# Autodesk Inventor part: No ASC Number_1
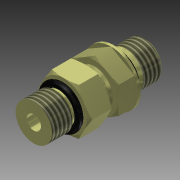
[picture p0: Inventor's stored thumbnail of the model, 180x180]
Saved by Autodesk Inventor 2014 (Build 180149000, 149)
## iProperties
Shininess: 20.0
Length Units: 11272
Angle Units: 11279
Time Units: 11290
Mass Units: 11286
Length Display Precision: 3
Angle Display Precision: 2
Company: Autodesk, Inc.
Created: 2001-10
Part Number: No ASC Number_1
Material: Steel, Mild
Description: FITTING; ST-GG4-S
Vendor: 0503-4-4
Document SubType Name: Modeling
Designer: Autodesk, Inc.
Density: 7.86 g/cm^3
Appearance: Yellow Zinc
Density: 7.86
Volumn: 2.786291585014959
Area: 20.936420168139023
PropertySet Name: Model Information
Control State: 0
Master: False
Checked Out: False
Last Check In By: JT
Last Check In Date: 2003-06-20
MODEL - 1: ---
MODEL - 2: ---
RAW MATERIAL: --------
SCALE:: 1=??
SIZE: 00 x 00 x 00
SUB-ASSY - 1: ------
SUB-ASSY - 1 - QUA: 1
SUB-ASSY - 2: ------
SUB-ASSY - 2 - QUA: 1
SYM. TO:: N/A
TEMPLATE CREATION: -- / __-__-__
Title: FITTING; ST-GG4-S
Author: Autodesk, Inc.
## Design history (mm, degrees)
sketch "Sketch1"
  geometry: L1 (8.249, 0)-(4.124, -7.144); L2 (4.124, -7.144)-(-4.124, -7.144); L3 (-4.124, -7.144)-(-8.249, 0); L4 (-8.249, 0)-(-4.124, 7.144); L5 (-4.124, 7.144)-(4.124, 7.144); L6 (4.124, 7.144)-(8.249, 0); 2 further points
  constraints: 12 end point, 1 coincident, 11 other
  dimensions: "d3" = 14.2875 distance between parallel lines of L3 L6 (= Hex_Size)
extrude "Hex Head" new body sketch "Sketch1" distance "d4" = 6.858 (= Hex_Thk); taper "d5" = 0 deg
sketch "Sketch2"
  geometry: L1 (-4.124, 6.858)-(-8.249, 6.858) reference; L2 (-4.124, 0)-(-8.249, 0) reference; L3 (-7.144, 0)-(-8.249, 0.515); L4 (-7.144, 6.858)-(-8.249, 6.343); L5 (-8.249, 6.858)-(-8.249, 6.343); L6 (-8.249, 0.515)-(-8.249, 0); L7 (-7.144, 6.858)-(-7.144, 0); L8 (0, 0)-(0, -4.932)
  constraints: 12 end point, 2 parallel, 2 perpendicular, 2 point on line
  dimensions: "d6" = 25 deg angle of L3 L2; "d7" = 25 deg angle of L1 L4; "d8" = 14.2875 diameter of L7 L8 (= Hex_Size)
revolve "Hex Head Material Removal" sketch "Sketch2" stored, may be unused: angle "d9" = 90 deg
sketch "Sketch8"
  geometry: L1 (0, 0)-(0, 19.901); L2 (4.623, 6.858)-(4.623, 8.839); L3 (4.623, 8.839)-(5.556, 9.773); L4 (5.556, 9.773)-(5.556, 16.002); L5 (5.556, 16.002)-(0, 16.002); L6 (4.124, 6.858)-(8.249, 6.858) reference; L7 (-4.124, 6.858)-(4.124, 6.858) reference; L8 (4.623, 6.858)-(0, 6.858); L9 (0, 6.858)-(0, 16.002)
  constraints: 14 end point, 1 collinear, 1 midpoint, 1 parallel, 1 perpendicular, 1 point on line, 1 vertical
  dimensions: "d31" = 11.1125 diameter of L4 L1 (= Oring_Thread_OD); "d32" = 9.2456 diameter of L2 L1 (= Oring_OD); "d33" = 7.1628 distance from line of L5 L2.end (= Oring_ThreadLength); "d35" = 45 deg angle of L2 L3; "d46" = 9.144 distance between parallel lines of L5 L6 (= Oring_Length)
revolve "Oring" sketch "Sketch8" stored, may be unused: angle "d36" = 90 deg
sketch "Sketch9"
  geometry: C1 r 5.556 at (0, 0) reference; C2 r 2.184 at (0, 0)
  constraints: 1 centre point, 1 coincident
  dimensions: "d37" = 4.3688 diameter of C2 (= Oring_ID)
extrude "Oring Hole" cut sketch "Sketch9" distance "d38" = 9.144 (= Oring_Length); taper "d39" = 0 deg
thread "Thread3" dims "d40" = 25.4, "d41" = 0
sketch "Sketch10"
  geometry: L1 (0, 0)-(0, 22.019); C1 r 0.953 at (5.575, 7.811)
  constraints: 2 end point, 1 centre point, 1 vertical
  dimensions: "d42" = 1.905 diameter of C1 (= Seal_Dia_W); "d43" = 7.8105 vertical distance of C1.centre L1.start (= Seal_Loc_A); "d44" = 5.5753 horizontal distance of C1.centre L1.start (= Seal_Loc_B)
revolve "Revolution4" sketch "Sketch10" stored, may be unused: angle "d45" = 90 deg
sketch "Sketch11"
  geometry: L1 (0, 0)-(0, -35.917); L2 (1.975, 0)-(1.975, 0); L3 (5.556, -2.81)-(5.556, -6.689); L4 (5.556, -6.689)-(4.648, -7.214); L5 (4.648, -7.214)-(4.648, -11.024); L6 (4.648, -11.024)-(5.556, -11.932); L7 (5.556, -11.932)-(5.556, -17.431); L8 (5.556, -17.431)-(4.699, -18.288); L9 (4.699, -18.288)-(0, -18.288); L10 (4.648, 0)-(4.648, -2.286); L11 (4.648, -2.286)-(5.556, -2.81); L12 (0, -18.288)-(0, 0); L13 (0, 0)-(4.648, 0); L14 (-5.556, 16.002)-(5.556, 16.002) reference
  constraints: 26 end point, 4 vertical, 3 perpendicular, 2 collinear, 1 point on line
  dimensions: "d52" = 60 deg angle of L5 L4; "d53" = 45 deg angle of L6 L5; "d54" = 60 deg angle of L3 L11; "d56" = 2.286 distance of L10.start L10.end (= Oring_Undercut_H_2); "d57" = 3.81 distance of L4.end L5.end (= Oring_Undercut_H1_2); "d58" = 9.2964 diameter of L10 L1 (= Oring_Undercut_G_2); "d59" = 9.2964 diameter of L5 L1 (= Oring_Undercut_G1_2); "d60" = 11.1125 diameter of L7 L1 (= Oring_Thread_OD_2); "d61" = 9.398 diameter of L8.end L1 (= Oring_Lip_V_2); "d63" = 7.2644 vertical distance of L8.end L5.end (= Oring_Threadlength_J3_2); "d64" = 18.288 distance from line of L9 L1.start (= I5_2)
revolve "Revolution5" sketch "Sketch11" stored, may be unused: angle "d62" = 90 deg
workplane "Work Plane1"
sketch "Sketch12"
  geometry: L1 (0, 8.249)-(7.144, 4.124); L2 (7.144, 4.124)-(7.144, -4.124); L3 (7.144, -4.124)-(0, -8.249); L4 (0, -8.249)-(-7.144, -4.124); L5 (-7.144, -4.124)-(-7.144, 4.124); L6 (-7.144, 4.124)-(0, 8.249); C1 r 5.556 at (0, 0); 2 further points
  constraints: 12 end point, 2 coincident, 1 centre point, 1 vertical alignment, 11 other
  dimensions: "d66" = 14.2875 distance between parallel lines of L6 L3 (derived); "d67" = 11.1125 diameter of C1 (derived)
extrude "Extrusion7" join sketch "Sketch12" distance "d68" = 5.842 (derived); taper "d69" = 0 deg
sketch "Sketch13"
  geometry: L1 (-4.699, -18.288)-(4.699, -18.288) reference; L2 (-13.494, -8.382)-(-7.144, -8.382); L3 (-7.144, -8.382)-(-13.494, -6.681); L4 (-13.494, -6.681)-(-13.494, -8.382); L5 (-7.144, -2.54)-(-13.494, -2.54); L6 (-13.494, -2.54)-(-13.494, -4.241); L7 (-13.494, -4.241)-(-7.144, -2.54); L8 (-7.144, -8.382)-(-7.144, -2.54); L9 (0, 0)-(0, -30.431)
  constraints: 16 end point, 3 parallel, 3 perpendicular, 1 collinear
  dimensions: "d70" = 15 deg angle of L3 L2; "d71" = 15 deg angle of L5 L7; "d72" = 14.2875 diameter of L8 L9 (derived); "d73" = 6.35 distance from line of L2.start L8; "d74" = 9.906 distance between parallel lines of L2 L1 (derived); "d75" = 5.842 distance between parallel lines of L5 L2 (derived)
revolve "Revolution6" sketch "Sketch13" stored, may be unused: angle "d76" = 90 deg
sketch "Sketch14"
  geometry: L1 (0, -8.249)-(3.572, -6.187) reference; L2 (3.572, -6.187)-(7.144, -4.124) reference; C1 r 5.556 at (0, 0); 2 further points
  constraints: 2 coincident, 1 centre point, 1 vertical alignment, 2 other
  dimensions: "d77" = 11.1125 diameter of C1 (derived)
extrude "Extrusion8" join sketch "Sketch14" distance "d79" = 0.79375; taper "d80" = 0 deg
thread "Thread4" dims "d81" = 25.4, "d82" = 0
sketch "Sketch15"
  geometry: L1 (-4.699, -18.288)-(4.699, -18.288) reference; L2 (0, 0)-(0, -23.609); C1 r 0.953 at (-5.601, -9.334)
  constraints: 2 end point, 1 centre point, 1 perpendicular
  dimensions: "d83" = 1.905 diameter of C1 (derived); "d84" = 8.9535 distance from line of C1.centre L1 (derived); "d85" = 11.2014 diameter of C1.centre L2 (derived)
revolve "Revolution7" sketch "Sketch15" stored, may be unused: angle "d86" = 90 deg
sketch "Sketch16"
  geometry: C1 r 2.184 at (0, 0); 1 further point
  constraints: 1 centre point, 1 coincident
  dimensions: "d87" = 4.3688 diameter of C1 (derived)
extrude "Extrusion9" cut sketch "Sketch16" distance "d88" = 25.146 (derived); taper "d89" = 0 deg
body "Solid1"
other parameters: "Hex_Size" = 14.2875 [user parameter; used in 2 equation terms], "Hex_Thk" = 6.858 [user parameter; used in 3 equation terms], "Jic_Length" = 15.24 (= Length_LL - Hex_Thk) [user parameter], "Jic_ThreadLength" = 7.1628 [user parameter], "Length_LL" = 22.098 [user parameter; used in 2 equation terms], "Jic_Thread_OD" = 11.1125 [user parameter], "JIC_OD" = 9.2456 [user parameter], "Jic_Lip_OD" = 4.9022 [user parameter], "Jic_ID" = 4.3688 [user parameter], "Oring_Length" = 9.144 (= OAL_L5 - Length_LL) [user parameter; used in 2 equation terms], "OAL_L5" = 31.242 [user parameter; used in 1 equation term], "Oring_Thread_OD" = 11.1125 [user parameter; used in 1 equation term], "Oring_ID" = 4.3688 [user parameter; used in 1 equation term], "Oring_OD" = 9.2456 [user parameter; used in 2 equation terms], "Oring_ThreadLength" = 7.1628 [user parameter; used in 1 equation term], "Seal_Dia_W" = 1.905 [user parameter; used in 3 equation terms], "Seal_Loc_A" = 7.8105 (= Hex_Thk + 0.5 x Seal_Dia_W) [user parameter; used in 1 equation term], "Seal_Loc_B" = 5.5753 (= 0.5 x Oring_OD + 0.5 x Seal_Dia_W) [user parameter; used in 1 equation term], "I5_2" = 18.288 [user parameter; used in 1 equation term], "Oring_Thread_OD_2" = 11.1125 [user parameter; used in 1 equation term], "Oring_Undercut_G_2" = 9.2964 [user parameter; used in 1 equation term], "Oring_Undercut_G1_2" = 9.2964 [user parameter; used in 1 equation term], "Oring_Threadlength_J3_2" = 7.2644 [user parameter; used in 1 equation term], "Oring_Undercut_H_2" = 2.286 [user parameter; used in 1 equation term], "Oring_Undercut_H1_2" = 3.81 [user parameter; used in 1 equation term], "Oring_Lip_V_2" = 9.398 [user parameter; used in 1 equation term], "Install_Depth_TE" = 9.906 [user parameter], "d65" = -9.906 (derived), "Hex_Thk_2" = 5.842 [user parameter], "Oring_ID_2" = 4.3688 [user parameter], "Hex_Size_2" = 14.2875 [user parameter]
